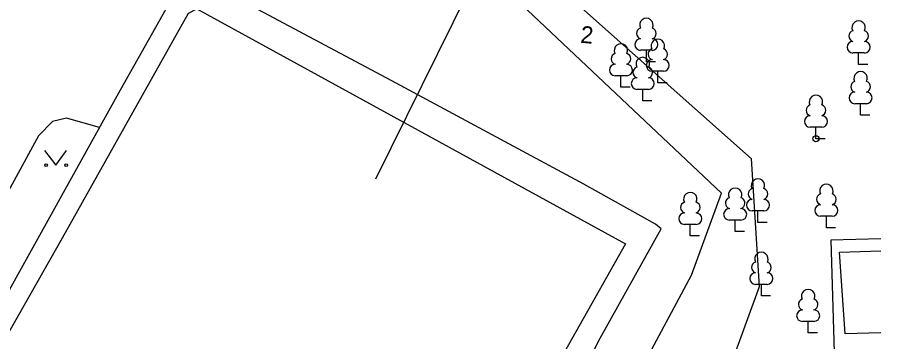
# Model space of a CAD drawing. Extents: x 713540 to 713867, y 6589774 to 6590061.
# Drawn here: x 713831.07 to 713866.67, y 6589908.24 to 6589921.62 of the extents above; entities that cross this region are included whole.
import ezdxf

# ---------------------------------------------------------------- set-up
doc = ezdxf.new("R2010")
doc.units = 0
for name, color, linetype in [('AED', 7, 'Continuous'), ('HALJASTUS', 7, 'Continuous'), ('HOONE', 7, 'Continuous'), ('HOONEDET', 7, 'Continuous'), ('KORGUS', 7, 'Continuous'), ('KTRASS', 7, 'Continuous'), ('PUU', 7, 'Continuous'), ('SKTRASS', 7, 'Continuous'), ('TEE', 7, 'Continuous'), ('TORU NR', 7, 'Continuous'), ('VEEKOGU', 7, 'Continuous')]:
    doc.layers.add(name, color=color, linetype=linetype)

msp = doc.modelspace()

# ---------------------------------------------------------------- linework, layer by layer
at = {"layer": 'AED'}
msp.add_lwpolyline([(713866.671, 6589912.481), (713864.61, 6589912.43), (713864.76, 6589907.34)], dxfattribs=at)
at = {"layer": 'HALJASTUS'}
for p, q in [((713832.197, 6589916.127), (713832.66, 6589915.52)), ((713832.66, 6589915.52), (713833.106, 6589916.127))]:
    msp.add_line(p, q, dxfattribs=at)
msp.add_lwpolyline([(713850.94, 6589925.26), (713845.84, 6589914.94)], dxfattribs=at)
for centre in [(713832.259, 6589915.52), (713833.088, 6589915.52)]:
    msp.add_circle(centre, 0.055, dxfattribs=at)
at = {"layer": 'HOONE'}
msp.add_lwpolyline([(713856.15, 6589912.28), (713845.91, 6589894.13), (713837.77, 6589879.4), (713837.43, 6589878.96), (713832.83, 6589881.48), (713819.45, 6589888.61), (713819.6, 6589888.94), (713824.63, 6589897.88), (713832.94, 6589912.52), (713838.13, 6589921.78), (713838.47, 6589921.97), (713856.15, 6589912.28)], dxfattribs=at)
at = {"layer": 'HOONEDET'}
msp.add_lwpolyline([(713844.4, 6589889.19), (713845.66, 6589891.64), (713849.44, 6589898.23), (713853.12, 6589904.55), (713855.1, 6589908.38), (713857.62, 6589912.89), (713857.38, 6589913.08), (713854.43, 6589914.73), (713846.51, 6589918.99), (713840.16, 6589922.39), (713838.17, 6589923.4), (713838.03, 6589923.31), (713837.2, 6589921.95), (713835.31, 6589918.61), (713828.38, 6589906.13), (713826.7, 6589903.28)], dxfattribs=at)
at = {"layer": 'KORGUS'}
msp.add_circle((713864, 6589916.61), 0.125, dxfattribs=at)
at = {"layer": 'KTRASS'}
msp.add_lwpolyline([(713856.57, 6589896.53), (713861.67, 6589910.52), (713861.34, 6589915.78), (713854.21, 6589922.12)], dxfattribs=at)
at = {"layer": 'PUU'}
for p, q in [((713857.25, 6589920.255), (713856.77, 6589920.255)), ((713857.01, 6589919.78), (713857.01, 6589920.255)), ((713866, 6589920.145), (713865.52, 6589920.145)), ((713865.76, 6589919.67), (713865.76, 6589920.145)), ((713857.39, 6589919.78), (713857.01, 6589919.78)), ((713866.14, 6589919.67), (713865.76, 6589919.67)), ((713856.2, 6589919.205), (713855.72, 6589919.205)), ((713855.96, 6589918.73), (713855.96, 6589919.205)), ((713857.72, 6589919.395), (713857.24, 6589919.395)), ((713857.48, 6589918.92), (713857.48, 6589919.395)), ((713857.86, 6589918.92), (713857.48, 6589918.92)), ((713856.34, 6589918.73), (713855.96, 6589918.73)), ((713857.1, 6589918.645), (713856.62, 6589918.645)), ((713856.86, 6589918.17), (713856.86, 6589918.645)), ((713857.24, 6589918.17), (713856.86, 6589918.17)), ((713866.08, 6589918.055), (713865.6, 6589918.055)), ((713865.84, 6589917.58), (713865.84, 6589918.055)), ((713866.22, 6589917.58), (713865.84, 6589917.58)), ((713864.24, 6589917.085), (713863.76, 6589917.085)), ((713864, 6589916.61), (713864, 6589917.085)), ((713864.38, 6589916.61), (713864, 6589916.61)), ((713861.85, 6589913.635), (713861.37, 6589913.635)), ((713861.61, 6589913.16), (713861.61, 6589913.635)), ((713860.91, 6589913.255), (713860.43, 6589913.255)), ((713860.67, 6589912.78), (713860.67, 6589913.255)), ((713861.99, 6589913.16), (713861.61, 6589913.16)), ((713864.67, 6589913.415), (713864.19, 6589913.415)), ((713864.43, 6589912.94), (713864.43, 6589913.415)), ((713859.06, 6589913.075), (713858.58, 6589913.075)), ((713858.82, 6589912.6), (713858.82, 6589913.075)), ((713861.05, 6589912.78), (713860.67, 6589912.78)), ((713864.81, 6589912.94), (713864.43, 6589912.94)), ((713859.2, 6589912.6), (713858.82, 6589912.6)), ((713861.99, 6589910.605), (713861.51, 6589910.605)), ((713861.75, 6589910.13), (713861.75, 6589910.605)), ((713862.13, 6589910.13), (713861.75, 6589910.13)), ((713863.92, 6589909.075), (713863.44, 6589909.075)), ((713863.68, 6589908.6), (713863.68, 6589909.075)), ((713864.06, 6589908.6), (713863.68, 6589908.6))]:
    msp.add_line(p, q, dxfattribs=at)
for centre, radius, start, end in [((713857.01, 6589921.3), 0.277, 332.5799, 207.4201), ((713865.76, 6589921.19), 0.277, 332.5799, 207.4201), ((713856.84, 6589920.953), 0.233, 109.0217, 253.1415), ((713857.18, 6589920.953), 0.233, 286.8508, 70.9859), ((713865.59, 6589920.843), 0.233, 109.0217, 253.1415), ((713865.93, 6589920.843), 0.233, 286.8508, 70.9859), ((713856.773, 6589920.492), 0.238, 90.0016, 269.3953), ((713857.48, 6589920.44), 0.277, 332.5799, 207.4201), ((713857.247, 6589920.492), 0.238, 270.6047, 89.9984), ((713865.523, 6589920.382), 0.238, 90.0016, 269.3953), ((713865.997, 6589920.382), 0.238, 270.6047, 89.9984), ((713855.96, 6589920.25), 0.277, 332.5799, 207.4201), ((713857.31, 6589920.093), 0.233, 109.0217, 253.1415), ((713857.65, 6589920.093), 0.233, 286.8508, 70.9859), ((713855.79, 6589919.903), 0.233, 109.0217, 253.1415), ((713856.13, 6589919.903), 0.233, 286.8508, 70.9859), ((713856.86, 6589919.69), 0.277, 332.5799, 207.4201), ((713855.723, 6589919.442), 0.238, 90.0016, 269.3953), ((713856.197, 6589919.442), 0.238, 270.6047, 89.9984), ((713856.69, 6589919.343), 0.233, 109.0217, 253.1415), ((713857.243, 6589919.632), 0.238, 90.0016, 269.3953), ((713857.03, 6589919.343), 0.233, 286.8508, 70.9859), ((713857.717, 6589919.632), 0.238, 270.6047, 89.9984), ((713865.84, 6589919.1), 0.277, 332.5799, 207.4201), ((713856.623, 6589918.882), 0.238, 90.0016, 269.3953), ((713857.097, 6589918.882), 0.238, 270.6047, 89.9984), ((713865.67, 6589918.753), 0.233, 109.0217, 253.1415), ((713866.01, 6589918.753), 0.233, 286.8508, 70.9859), ((713865.603, 6589918.292), 0.238, 90.0016, 269.3953), ((713866.077, 6589918.292), 0.238, 270.6047, 89.9984), ((713864, 6589918.13), 0.277, 332.5799, 207.4201), ((713863.83, 6589917.783), 0.233, 109.0217, 253.1415), ((713864.17, 6589917.783), 0.233, 286.8508, 70.9859), ((713863.763, 6589917.322), 0.238, 90.0016, 269.3953), ((713864.237, 6589917.322), 0.238, 270.6047, 89.9984), ((713861.61, 6589914.68), 0.277, 332.5799, 207.4201), ((713860.67, 6589914.3), 0.277, 332.5799, 207.4201), ((713861.44, 6589914.333), 0.233, 109.0217, 253.1415), ((713861.78, 6589914.333), 0.233, 286.8508, 70.9859), ((713864.43, 6589914.46), 0.277, 332.5799, 207.4201), ((713858.82, 6589914.12), 0.277, 332.5799, 207.4201), ((713864.26, 6589914.113), 0.233, 109.0217, 253.1415), ((713864.6, 6589914.113), 0.233, 286.8508, 70.9859), ((713858.65, 6589913.773), 0.233, 109.0217, 253.1415), ((713858.99, 6589913.773), 0.233, 286.8508, 70.9859), ((713860.5, 6589913.953), 0.233, 109.0217, 253.1415), ((713860.84, 6589913.953), 0.233, 286.8508, 70.9859), ((713861.373, 6589913.872), 0.238, 90.0016, 269.3953), ((713861.847, 6589913.872), 0.238, 270.6047, 89.9984), ((713864.193, 6589913.652), 0.238, 90.0016, 269.3953), ((713864.667, 6589913.652), 0.238, 270.6047, 89.9984), ((713858.583, 6589913.312), 0.238, 90.0016, 269.3953), ((713859.057, 6589913.312), 0.238, 270.6047, 89.9984), ((713860.433, 6589913.492), 0.238, 90.0016, 269.3953), ((713860.907, 6589913.492), 0.238, 270.6047, 89.9984), ((713861.75, 6589911.65), 0.277, 332.5799, 207.4201), ((713861.58, 6589911.303), 0.233, 109.0217, 253.1415), ((713861.92, 6589911.303), 0.233, 286.8508, 70.9859), ((713861.513, 6589910.842), 0.238, 90.0016, 269.3953), ((713861.987, 6589910.842), 0.238, 270.6047, 89.9984), ((713863.68, 6589910.12), 0.277, 332.5799, 207.4201), ((713863.51, 6589909.773), 0.233, 109.0217, 253.1415), ((713863.85, 6589909.773), 0.233, 286.8508, 70.9859), ((713863.443, 6589909.312), 0.238, 90.0016, 269.3953), ((713863.917, 6589909.312), 0.238, 270.6047, 89.9984)]:
    msp.add_arc(centre, radius, start, end, dxfattribs=at)
at = {"layer": 'SKTRASS'}
msp.add_lwpolyline([(713837.821, 6589871.685), (713858.87, 6589910.99), (713860.1, 6589914.37), (713852.11, 6589921.91), (713866.671, 6589948.059)], dxfattribs=at)
at = {"layer": 'TEE'}
msp.add_lwpolyline([(713834.47, 6589917.07), (713833.11, 6589917.46), (713832.53, 6589917.32), (713831.95, 6589916.73), (713828.84, 6589911.05), (713826.78, 6589907.56), (713825.89, 6589905.95), (713825.5, 6589905.13), (713825.5, 6589904.74), (713825.64, 6589904.12), (713825.84, 6589903.72), (713826.02, 6589903.54), (713826.71, 6589903.29)], dxfattribs=at)
at = {"layer": 'VEEKOGU'}
for points in [[(713865.21, 6589908.56), (713864.97, 6589911.93), (713866.671, 6589911.983)], [(713866.671, 6589908.606), (713865.2, 6589908.56)]]:
    msp.add_lwpolyline(points, dxfattribs=at)

# ---------------------------------------------------------------- texts
at = {"layer": 'TORU NR'}
msp.add_text('2', height=0.7, rotation=354.7103, dxfattribs=at).set_placement((713854.271, 6589920.57))

doc.saveas('drawing.dxf')
